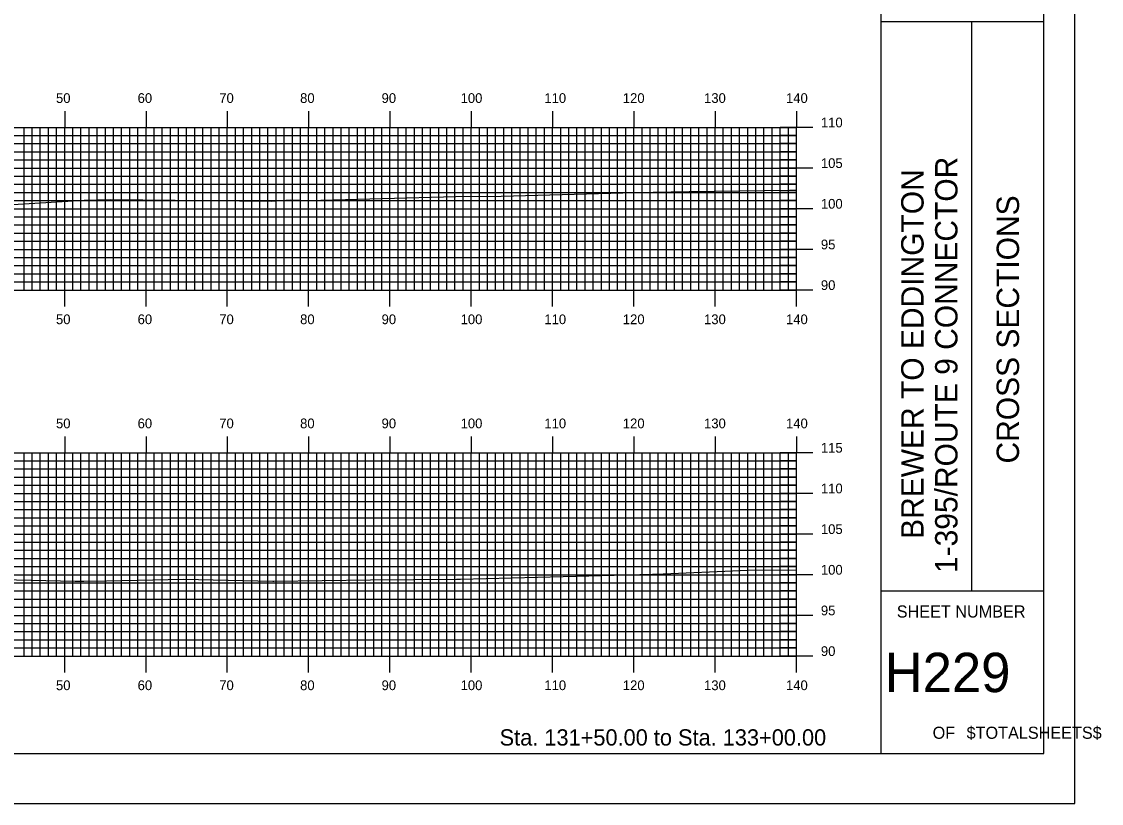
# Model space of a CAD drawing. Extents: x 1774383 to 1774727, y 442591 to 442811.
# Drawn here: x 1774593.9 to 1774726.7, y 442590.5 to 442686.7 of the extents above; entities that cross this region are included whole.
import ezdxf

# ---------------------------------------------------------------- set-up
doc = ezdxf.new("R2010")
doc.units = 0
for name, color, linetype in [('BORDER', 7, 'Continuous'), ('H_V ANNOTATION', 7, 'Continuous'), ('MAJOR', 7, 'Continuous'), ('MINOR', 7, 'Continuous'), ('PLOT BOUNDARY', 7, 'Continuous'), ('S_Roadway_Centerline', 7, 'Continuous')]:
    doc.layers.add(name, color=color, linetype=linetype)

msp = doc.modelspace()

# ---------------------------------------------------------------- linework, layer by layer
at = {"layer": 'BORDER'}
for p, q in [((1774699.57, 442596.67), (1774699.57, 442806.67)), ((1774699.57, 442686.67), (1774719.57, 442686.67)), ((1774710.75, 442616.67), (1774710.75, 442686.67)), ((1774699.57, 442616.67), (1774719.57, 442616.67))]:
    msp.add_line(p, q, dxfattribs=at)
msp.add_lwpolyline([(1774399.57, 442596.67), (1774719.57, 442596.67), (1774719.57, 442806.67), (1774399.57, 442806.67)], close=True, dxfattribs=at)
at = {"layer": 'MAJOR'}
for p, q in [((1774599.17, 442675.67), (1774599.17, 442673.67)), ((1774609.17, 442675.67), (1774609.17, 442673.67)), ((1774619.17, 442675.67), (1774619.17, 442673.67)), ((1774629.17, 442675.67), (1774629.17, 442673.67)), ((1774639.17, 442675.67), (1774639.17, 442673.67)), ((1774649.17, 442675.67), (1774649.17, 442673.67)), ((1774659.17, 442675.67), (1774659.17, 442673.67)), ((1774669.17, 442675.67), (1774669.17, 442673.67)), ((1774679.17, 442675.67), (1774679.17, 442673.67)), ((1774689.17, 442675.67), (1774689.17, 442673.67)), ((1774409.17, 442673.67), (1774689.17, 442673.67)), ((1774409.17, 442673.67), (1774689.17, 442673.67)), ((1774599.17, 442653.67), (1774599.17, 442673.67)), ((1774609.17, 442653.67), (1774609.17, 442673.67)), ((1774619.17, 442653.67), (1774619.17, 442673.67)), ((1774629.17, 442653.67), (1774629.17, 442673.67)), ((1774639.17, 442653.67), (1774639.17, 442673.67)), ((1774649.17, 442653.67), (1774649.17, 442673.67)), ((1774659.17, 442653.67), (1774659.17, 442673.67)), ((1774669.17, 442653.67), (1774669.17, 442673.67)), ((1774679.17, 442653.67), (1774679.17, 442673.67)), ((1774691.18, 442673.67), (1774687.17, 442673.67)), ((1774689.17, 442653.67), (1774689.17, 442673.67)), ((1774689.17, 442653.67), (1774689.17, 442673.67)), ((1774409.17, 442668.67), (1774689.17, 442668.67)), ((1774691.18, 442668.67), (1774687.17, 442668.67)), ((1774409.17, 442663.67), (1774689.17, 442663.67)), ((1774691.18, 442663.67), (1774687.17, 442663.67)), ((1774409.17, 442658.67), (1774689.17, 442658.67)), ((1774691.18, 442658.67), (1774687.17, 442658.67)), ((1774409.17, 442653.67), (1774689.17, 442653.67)), ((1774409.17, 442653.67), (1774689.17, 442653.67)), ((1774599.17, 442651.66), (1774599.17, 442653.67)), ((1774609.17, 442651.66), (1774609.17, 442653.67)), ((1774619.17, 442651.66), (1774619.17, 442653.67)), ((1774629.17, 442651.66), (1774629.17, 442653.67)), ((1774639.17, 442651.66), (1774639.17, 442653.67)), ((1774649.17, 442651.66), (1774649.17, 442653.67)), ((1774659.17, 442651.66), (1774659.17, 442653.67)), ((1774669.17, 442651.66), (1774669.17, 442653.67)), ((1774679.17, 442651.66), (1774679.17, 442653.67)), ((1774691.18, 442653.67), (1774687.17, 442653.67)), ((1774689.17, 442651.66), (1774689.17, 442653.67)), ((1774599.17, 442635.67), (1774599.17, 442633.67)), ((1774609.17, 442635.67), (1774609.17, 442633.67)), ((1774619.17, 442635.67), (1774619.17, 442633.67)), ((1774629.17, 442635.67), (1774629.17, 442633.67)), ((1774639.17, 442635.67), (1774639.17, 442633.67)), ((1774649.17, 442635.67), (1774649.17, 442633.67)), ((1774659.17, 442635.67), (1774659.17, 442633.67)), ((1774669.17, 442635.67), (1774669.17, 442633.67)), ((1774679.17, 442635.67), (1774679.17, 442633.67)), ((1774689.17, 442635.67), (1774689.17, 442633.67)), ((1774409.17, 442633.67), (1774689.17, 442633.67)), ((1774409.17, 442633.67), (1774689.17, 442633.67)), ((1774599.17, 442608.67), (1774599.17, 442633.67)), ((1774609.17, 442608.67), (1774609.17, 442633.67)), ((1774619.17, 442608.67), (1774619.17, 442633.67)), ((1774629.17, 442608.67), (1774629.17, 442633.67)), ((1774639.17, 442608.67), (1774639.17, 442633.67)), ((1774649.17, 442608.67), (1774649.17, 442633.67)), ((1774659.17, 442608.67), (1774659.17, 442633.67)), ((1774669.17, 442608.67), (1774669.17, 442633.67)), ((1774679.17, 442608.67), (1774679.17, 442633.67)), ((1774691.18, 442633.67), (1774687.17, 442633.67)), ((1774689.17, 442608.67), (1774689.17, 442633.67)), ((1774689.17, 442608.67), (1774689.17, 442633.67)), ((1774409.17, 442628.67), (1774689.17, 442628.67)), ((1774691.18, 442628.67), (1774687.17, 442628.67)), ((1774409.17, 442623.67), (1774689.17, 442623.67)), ((1774691.18, 442623.67), (1774687.17, 442623.67)), ((1774409.17, 442618.67), (1774689.17, 442618.67)), ((1774691.18, 442618.67), (1774687.17, 442618.67)), ((1774409.17, 442613.67), (1774689.17, 442613.67)), ((1774691.18, 442613.67), (1774687.17, 442613.67)), ((1774409.17, 442608.67), (1774689.17, 442608.67)), ((1774409.17, 442608.67), (1774689.17, 442608.67)), ((1774599.17, 442606.66), (1774599.17, 442608.67)), ((1774609.17, 442606.66), (1774609.17, 442608.67)), ((1774619.17, 442606.66), (1774619.17, 442608.67)), ((1774629.17, 442606.66), (1774629.17, 442608.67)), ((1774639.17, 442606.66), (1774639.17, 442608.67)), ((1774649.17, 442606.66), (1774649.17, 442608.67)), ((1774659.17, 442606.66), (1774659.17, 442608.67)), ((1774669.17, 442606.66), (1774669.17, 442608.67)), ((1774679.17, 442606.66), (1774679.17, 442608.67)), ((1774691.18, 442608.67), (1774687.17, 442608.67)), ((1774689.17, 442606.66), (1774689.17, 442608.67))]:
    msp.add_line(p, q, dxfattribs=at)
at = {"layer": 'MINOR'}
for p, q in [((1774594.17, 442653.67), (1774594.17, 442673.67)), ((1774595.17, 442653.67), (1774595.17, 442673.67)), ((1774596.17, 442653.67), (1774596.17, 442673.67)), ((1774597.17, 442653.67), (1774597.17, 442673.67)), ((1774598.17, 442653.67), (1774598.17, 442673.67)), ((1774600.17, 442653.67), (1774600.17, 442673.67)), ((1774601.17, 442653.67), (1774601.17, 442673.67)), ((1774602.17, 442653.67), (1774602.17, 442673.67)), ((1774603.17, 442653.67), (1774603.17, 442673.67)), ((1774604.17, 442653.67), (1774604.17, 442673.67)), ((1774605.17, 442653.67), (1774605.17, 442673.67)), ((1774606.17, 442653.67), (1774606.17, 442673.67)), ((1774607.17, 442653.67), (1774607.17, 442673.67)), ((1774608.17, 442653.67), (1774608.17, 442673.67)), ((1774610.17, 442653.67), (1774610.17, 442673.67)), ((1774611.17, 442653.67), (1774611.17, 442673.67)), ((1774612.17, 442653.67), (1774612.17, 442673.67)), ((1774613.17, 442653.67), (1774613.17, 442673.67)), ((1774614.17, 442653.67), (1774614.17, 442673.67)), ((1774615.17, 442653.67), (1774615.17, 442673.67)), ((1774616.17, 442653.67), (1774616.17, 442673.67)), ((1774617.17, 442653.67), (1774617.17, 442673.67)), ((1774618.17, 442653.67), (1774618.17, 442673.67)), ((1774620.17, 442653.67), (1774620.17, 442673.67)), ((1774621.17, 442653.67), (1774621.17, 442673.67)), ((1774622.17, 442653.67), (1774622.17, 442673.67)), ((1774623.17, 442653.67), (1774623.17, 442673.67)), ((1774624.17, 442653.67), (1774624.17, 442673.67)), ((1774625.17, 442653.67), (1774625.17, 442673.67)), ((1774626.17, 442653.67), (1774626.17, 442673.67)), ((1774627.17, 442653.67), (1774627.17, 442673.67)), ((1774628.17, 442653.67), (1774628.17, 442673.67)), ((1774630.17, 442653.67), (1774630.17, 442673.67)), ((1774631.17, 442653.67), (1774631.17, 442673.67)), ((1774632.17, 442653.67), (1774632.17, 442673.67)), ((1774633.17, 442653.67), (1774633.17, 442673.67)), ((1774634.17, 442653.67), (1774634.17, 442673.67)), ((1774635.17, 442653.67), (1774635.17, 442673.67)), ((1774636.17, 442653.67), (1774636.17, 442673.67)), ((1774637.17, 442653.67), (1774637.17, 442673.67)), ((1774638.17, 442653.67), (1774638.17, 442673.67)), ((1774640.17, 442653.67), (1774640.17, 442673.67)), ((1774641.17, 442653.67), (1774641.17, 442673.67)), ((1774642.17, 442653.67), (1774642.17, 442673.67)), ((1774643.17, 442653.67), (1774643.17, 442673.67)), ((1774644.17, 442653.67), (1774644.17, 442673.67)), ((1774645.17, 442653.67), (1774645.17, 442673.67)), ((1774646.17, 442653.67), (1774646.17, 442673.67)), ((1774647.17, 442653.67), (1774647.17, 442673.67)), ((1774648.17, 442653.67), (1774648.17, 442673.67)), ((1774650.17, 442653.67), (1774650.17, 442673.67)), ((1774651.17, 442653.67), (1774651.17, 442673.67)), ((1774652.17, 442653.67), (1774652.17, 442673.67)), ((1774653.17, 442653.67), (1774653.17, 442673.67)), ((1774654.17, 442653.67), (1774654.17, 442673.67)), ((1774655.17, 442653.67), (1774655.17, 442673.67)), ((1774656.17, 442653.67), (1774656.17, 442673.67)), ((1774657.17, 442653.67), (1774657.17, 442673.67)), ((1774658.17, 442653.67), (1774658.17, 442673.67)), ((1774660.17, 442653.67), (1774660.17, 442673.67)), ((1774661.17, 442653.67), (1774661.17, 442673.67)), ((1774662.17, 442653.67), (1774662.17, 442673.67)), ((1774663.17, 442653.67), (1774663.17, 442673.67)), ((1774664.17, 442653.67), (1774664.17, 442673.67)), ((1774665.17, 442653.67), (1774665.17, 442673.67)), ((1774666.17, 442653.67), (1774666.17, 442673.67)), ((1774667.17, 442653.67), (1774667.17, 442673.67)), ((1774668.17, 442653.67), (1774668.17, 442673.67)), ((1774670.17, 442653.67), (1774670.17, 442673.67)), ((1774671.17, 442653.67), (1774671.17, 442673.67)), ((1774672.17, 442653.67), (1774672.17, 442673.67)), ((1774673.17, 442653.67), (1774673.17, 442673.67)), ((1774674.17, 442653.67), (1774674.17, 442673.67)), ((1774675.17, 442653.67), (1774675.17, 442673.67)), ((1774676.17, 442653.67), (1774676.17, 442673.67)), ((1774677.17, 442653.67), (1774677.17, 442673.67)), ((1774678.17, 442653.67), (1774678.17, 442673.67)), ((1774680.17, 442653.67), (1774680.17, 442673.67)), ((1774681.17, 442653.67), (1774681.17, 442673.67)), ((1774682.17, 442653.67), (1774682.17, 442673.67)), ((1774683.17, 442653.67), (1774683.17, 442673.67)), ((1774684.17, 442653.67), (1774684.17, 442673.67)), ((1774685.17, 442653.67), (1774685.17, 442673.67)), ((1774686.17, 442653.67), (1774686.17, 442673.67)), ((1774687.17, 442653.67), (1774687.17, 442673.67)), ((1774688.17, 442653.67), (1774688.17, 442673.67)), ((1774409.17, 442672.67), (1774689.17, 442672.67)), ((1774409.17, 442671.67), (1774689.17, 442671.67)), ((1774689.17, 442672.67), (1774687.17, 442672.67)), ((1774689.17, 442671.67), (1774687.17, 442671.67)), ((1774409.17, 442670.67), (1774689.17, 442670.67)), ((1774689.17, 442670.67), (1774687.17, 442670.67)), ((1774409.17, 442669.67), (1774689.17, 442669.67)), ((1774689.17, 442669.67), (1774687.17, 442669.67)), ((1774409.17, 442667.67), (1774689.17, 442667.67)), ((1774689.17, 442667.67), (1774687.17, 442667.67)), ((1774409.17, 442666.67), (1774689.17, 442666.67)), ((1774689.17, 442666.67), (1774687.17, 442666.67)), ((1774409.17, 442665.67), (1774689.17, 442665.67)), ((1774689.17, 442665.67), (1774687.17, 442665.67)), ((1774409.17, 442664.67), (1774689.17, 442664.67)), ((1774689.17, 442664.67), (1774687.17, 442664.67)), ((1774409.17, 442662.67), (1774689.17, 442662.67)), ((1774689.17, 442662.67), (1774687.17, 442662.67)), ((1774409.17, 442661.67), (1774689.17, 442661.67)), ((1774689.17, 442661.67), (1774687.17, 442661.67)), ((1774409.17, 442660.67), (1774689.17, 442660.67)), ((1774409.17, 442659.67), (1774689.17, 442659.67)), ((1774689.17, 442660.67), (1774687.17, 442660.67)), ((1774689.17, 442659.67), (1774687.17, 442659.67)), ((1774409.17, 442657.67), (1774689.17, 442657.67)), ((1774689.17, 442657.67), (1774687.17, 442657.67)), ((1774409.17, 442656.67), (1774689.17, 442656.67)), ((1774409.17, 442655.67), (1774689.17, 442655.67)), ((1774689.17, 442656.67), (1774687.17, 442656.67)), ((1774689.17, 442655.67), (1774687.17, 442655.67)), ((1774409.17, 442654.67), (1774689.17, 442654.67)), ((1774689.17, 442654.67), (1774687.17, 442654.67)), ((1774594.17, 442608.67), (1774594.17, 442633.67)), ((1774595.17, 442608.67), (1774595.17, 442633.67)), ((1774596.17, 442608.67), (1774596.17, 442633.67)), ((1774597.17, 442608.67), (1774597.17, 442633.67)), ((1774598.17, 442608.67), (1774598.17, 442633.67)), ((1774600.17, 442608.67), (1774600.17, 442633.67)), ((1774601.17, 442608.67), (1774601.17, 442633.67)), ((1774602.17, 442608.67), (1774602.17, 442633.67)), ((1774603.17, 442608.67), (1774603.17, 442633.67)), ((1774604.17, 442608.67), (1774604.17, 442633.67)), ((1774605.17, 442608.67), (1774605.17, 442633.67)), ((1774606.17, 442608.67), (1774606.17, 442633.67)), ((1774607.17, 442608.67), (1774607.17, 442633.67)), ((1774608.17, 442608.67), (1774608.17, 442633.67)), ((1774610.17, 442608.67), (1774610.17, 442633.67)), ((1774611.17, 442608.67), (1774611.17, 442633.67)), ((1774612.17, 442608.67), (1774612.17, 442633.67)), ((1774613.17, 442608.67), (1774613.17, 442633.67)), ((1774614.17, 442608.67), (1774614.17, 442633.67)), ((1774615.17, 442608.67), (1774615.17, 442633.67)), ((1774616.17, 442608.67), (1774616.17, 442633.67)), ((1774617.17, 442608.67), (1774617.17, 442633.67)), ((1774618.17, 442608.67), (1774618.17, 442633.67)), ((1774620.17, 442608.67), (1774620.17, 442633.67)), ((1774621.17, 442608.67), (1774621.17, 442633.67)), ((1774622.17, 442608.67), (1774622.17, 442633.67)), ((1774623.17, 442608.67), (1774623.17, 442633.67)), ((1774624.17, 442608.67), (1774624.17, 442633.67)), ((1774625.17, 442608.67), (1774625.17, 442633.67)), ((1774626.17, 442608.67), (1774626.17, 442633.67)), ((1774627.17, 442608.67), (1774627.17, 442633.67)), ((1774628.17, 442608.67), (1774628.17, 442633.67)), ((1774630.17, 442608.67), (1774630.17, 442633.67)), ((1774631.17, 442608.67), (1774631.17, 442633.67)), ((1774632.17, 442608.67), (1774632.17, 442633.67)), ((1774633.17, 442608.67), (1774633.17, 442633.67)), ((1774634.17, 442608.67), (1774634.17, 442633.67)), ((1774635.17, 442608.67), (1774635.17, 442633.67)), ((1774636.17, 442608.67), (1774636.17, 442633.67)), ((1774637.17, 442608.67), (1774637.17, 442633.67)), ((1774638.17, 442608.67), (1774638.17, 442633.67)), ((1774640.17, 442608.67), (1774640.17, 442633.67)), ((1774641.17, 442608.67), (1774641.17, 442633.67)), ((1774642.17, 442608.67), (1774642.17, 442633.67)), ((1774643.17, 442608.67), (1774643.17, 442633.67)), ((1774644.17, 442608.67), (1774644.17, 442633.67)), ((1774645.17, 442608.67), (1774645.17, 442633.67)), ((1774646.17, 442608.67), (1774646.17, 442633.67)), ((1774647.17, 442608.67), (1774647.17, 442633.67)), ((1774648.17, 442608.67), (1774648.17, 442633.67)), ((1774650.17, 442608.67), (1774650.17, 442633.67)), ((1774651.17, 442608.67), (1774651.17, 442633.67)), ((1774652.17, 442608.67), (1774652.17, 442633.67)), ((1774653.17, 442608.67), (1774653.17, 442633.67)), ((1774654.17, 442608.67), (1774654.17, 442633.67)), ((1774655.17, 442608.67), (1774655.17, 442633.67)), ((1774656.17, 442608.67), (1774656.17, 442633.67)), ((1774657.17, 442608.67), (1774657.17, 442633.67)), ((1774658.17, 442608.67), (1774658.17, 442633.67)), ((1774660.17, 442608.67), (1774660.17, 442633.67)), ((1774661.17, 442608.67), (1774661.17, 442633.67)), ((1774662.17, 442608.67), (1774662.17, 442633.67)), ((1774663.17, 442608.67), (1774663.17, 442633.67)), ((1774664.17, 442608.67), (1774664.17, 442633.67)), ((1774665.17, 442608.67), (1774665.17, 442633.67)), ((1774666.17, 442608.67), (1774666.17, 442633.67)), ((1774667.17, 442608.67), (1774667.17, 442633.67)), ((1774668.17, 442608.67), (1774668.17, 442633.67)), ((1774670.17, 442608.67), (1774670.17, 442633.67)), ((1774671.17, 442608.67), (1774671.17, 442633.67)), ((1774672.17, 442608.67), (1774672.17, 442633.67)), ((1774673.17, 442608.67), (1774673.17, 442633.67)), ((1774674.17, 442608.67), (1774674.17, 442633.67)), ((1774675.17, 442608.67), (1774675.17, 442633.67)), ((1774676.17, 442608.67), (1774676.17, 442633.67)), ((1774677.17, 442608.67), (1774677.17, 442633.67)), ((1774678.17, 442608.67), (1774678.17, 442633.67)), ((1774680.17, 442608.67), (1774680.17, 442633.67)), ((1774681.17, 442608.67), (1774681.17, 442633.67)), ((1774682.17, 442608.67), (1774682.17, 442633.67)), ((1774683.17, 442608.67), (1774683.17, 442633.67)), ((1774684.17, 442608.67), (1774684.17, 442633.67)), ((1774685.17, 442608.67), (1774685.17, 442633.67)), ((1774686.17, 442608.67), (1774686.17, 442633.67)), ((1774687.17, 442608.67), (1774687.17, 442633.67)), ((1774688.17, 442608.67), (1774688.17, 442633.67)), ((1774409.17, 442632.67), (1774689.17, 442632.67)), ((1774689.17, 442632.67), (1774687.17, 442632.67)), ((1774409.17, 442631.67), (1774689.17, 442631.67)), ((1774409.17, 442630.67), (1774689.17, 442630.67)), ((1774689.17, 442631.67), (1774687.17, 442631.67)), ((1774689.17, 442630.67), (1774687.17, 442630.67)), ((1774409.17, 442629.67), (1774689.17, 442629.67)), ((1774689.17, 442629.67), (1774687.17, 442629.67)), ((1774409.17, 442627.67), (1774689.17, 442627.67)), ((1774409.17, 442626.67), (1774689.17, 442626.67)), ((1774689.17, 442627.67), (1774687.17, 442627.67)), ((1774689.17, 442626.67), (1774687.17, 442626.67)), ((1774409.17, 442625.67), (1774689.17, 442625.67)), ((1774689.17, 442625.67), (1774687.17, 442625.67)), ((1774409.17, 442624.67), (1774689.17, 442624.67)), ((1774689.17, 442624.67), (1774687.17, 442624.67)), ((1774409.17, 442622.67), (1774689.17, 442622.67)), ((1774689.17, 442622.67), (1774687.17, 442622.67)), ((1774409.17, 442621.67), (1774689.17, 442621.67)), ((1774689.17, 442621.67), (1774687.17, 442621.67)), ((1774409.17, 442620.67), (1774689.17, 442620.67)), ((1774689.17, 442620.67), (1774687.17, 442620.67)), ((1774409.17, 442619.67), (1774689.17, 442619.67)), ((1774689.17, 442619.67), (1774687.17, 442619.67)), ((1774409.17, 442617.67), (1774689.17, 442617.67)), ((1774689.17, 442617.67), (1774687.17, 442617.67)), ((1774409.17, 442616.67), (1774689.17, 442616.67)), ((1774689.17, 442616.67), (1774687.17, 442616.67)), ((1774409.17, 442615.67), (1774689.17, 442615.67)), ((1774409.17, 442614.67), (1774689.17, 442614.67)), ((1774689.17, 442615.67), (1774687.17, 442615.67)), ((1774689.17, 442614.67), (1774687.17, 442614.67)), ((1774409.17, 442612.67), (1774689.17, 442612.67)), ((1774689.17, 442612.67), (1774687.17, 442612.67)), ((1774409.17, 442611.67), (1774689.17, 442611.67)), ((1774409.17, 442610.67), (1774689.17, 442610.67)), ((1774689.17, 442611.67), (1774687.17, 442611.67)), ((1774689.17, 442610.67), (1774687.17, 442610.67)), ((1774409.17, 442609.67), (1774689.17, 442609.67)), ((1774689.17, 442609.67), (1774687.17, 442609.67))]:
    msp.add_line(p, q, dxfattribs=at)
at = {"layer": 'PLOT BOUNDARY'}
msp.add_lwpolyline([(1774383.39, 442590.55), (1774723.39, 442590.55), (1774723.39, 442810.55), (1774383.39, 442810.55)], close=True, dxfattribs=at)
at = {"layer": 'S_Roadway_Centerline'}
for points in [[(1774581.93, 442663.54), (1774601.55, 442664.72), (1774603.22, 442664.77), (1774604.86, 442664.79), (1774624.59, 442664.6), (1774626.96, 442664.74), (1774629.16, 442664.69), (1774647.26, 442665.15), (1774652.84, 442665.23), (1774669.33, 442665.67), (1774675.95, 442665.78), (1774688.29, 442665.95), (1774689.17, 442665.96)], [(1774578.72, 442618.36), (1774600.44, 442617.87), (1774601.53, 442617.87), (1774604.32, 442617.91), (1774613.77, 442618.13), (1774624.76, 442617.87), (1774624.87, 442617.87), (1774636.77, 442618.03), (1774647.35, 442618.1), (1774647.57, 442618.1), (1774647.85, 442618.1), (1774660.46, 442618.46), (1774671.47, 442618.74), (1774671.82, 442618.75), (1774683.18, 442619.24), (1774689.17, 442619.25)]]:
    msp.add_lwpolyline(points, dxfattribs=at)

# ---------------------------------------------------------------- texts
at = {"layer": 'BORDER'}
for s, p in [('1-395/ROUTE 9 CONNECTOR', (1774708.97, 442618.87)), ('BREWER TO EDDINGTON', (1774704.8, 442623.07)), ('CROSS SECTIONS', (1774716.54, 442632.34))]:
    msp.add_text(s, height=2.7557, rotation=90, dxfattribs=at).set_placement(p)
for s, height, p in [('SHEET NUMBER', 1.4905, (1774701.5, 442613.4)), ('H229', 4.839, (1774700.01, 442604.23)), ('OF', 1.491, (1774705.91, 442598.49)), ('$TOTALSHEETS$', 1.4905, (1774710.09, 442598.49))]:
    msp.add_text(s, height=height, dxfattribs=at).set_placement(p)
at = {"layer": 'H_V ANNOTATION'}
for s, height, p in [('50', 1.2, (1774598.1, 442676.67)), ('60', 1.2, (1774608.14, 442676.67)), ('70', 1.2, (1774618.18, 442676.67)), ('80', 1.2, (1774628.12, 442676.67)), ('90', 1.2, (1774638.14, 442676.67)), ('100', 1.2, (1774647.86, 442676.67)), ('110', 1.2, (1774658.16, 442676.67)), ('120', 1.2, (1774667.81, 442676.67)), ('130', 1.2, (1774677.8, 442676.67)), ('140', 1.2, (1774687.88, 442676.67)), ('110', 1.2, (1774692.17, 442673.67)), ('105', 1.2, (1774692.17, 442668.67)), ('100', 1.2, (1774692.17, 442663.67)), ('95', 1.2, (1774692.17, 442658.67)), ('90', 1.2, (1774692.17, 442653.67)), ('50', 1.2, (1774598.1, 442649.47)), ('60', 1.2, (1774608.14, 442649.47)), ('70', 1.2, (1774618.18, 442649.47)), ('80', 1.2, (1774628.12, 442649.47)), ('90', 1.2, (1774638.14, 442649.47)), ('100', 1.2, (1774647.86, 442649.47)), ('110', 1.2, (1774658.16, 442649.47)), ('120', 1.2, (1774667.81, 442649.47)), ('130', 1.2, (1774677.8, 442649.47)), ('140', 1.2, (1774687.88, 442649.47)), ('50', 1.2, (1774598.1, 442636.67)), ('60', 1.2, (1774608.14, 442636.67)), ('70', 1.2, (1774618.18, 442636.67)), ('80', 1.2, (1774628.12, 442636.67)), ('90', 1.2, (1774638.14, 442636.67)), ('100', 1.2, (1774647.86, 442636.67)), ('110', 1.2, (1774658.16, 442636.67)), ('120', 1.2, (1774667.81, 442636.67)), ('130', 1.2, (1774677.8, 442636.67)), ('140', 1.2, (1774687.88, 442636.67)), ('115', 1.2, (1774692.17, 442633.67)), ('110', 1.2, (1774692.17, 442628.67)), ('105', 1.2, (1774692.17, 442623.67)), ('100', 1.2, (1774692.17, 442618.67)), ('95', 1.2, (1774692.17, 442613.67)), ('90', 1.2, (1774692.17, 442608.67)), ('50', 1.2, (1774598.1, 442604.47)), ('60', 1.2, (1774608.14, 442604.47)), ('70', 1.2, (1774618.18, 442604.47)), ('80', 1.2, (1774628.12, 442604.47)), ('90', 1.2, (1774638.14, 442604.47)), ('100', 1.2, (1774647.86, 442604.47)), ('110', 1.2, (1774658.16, 442604.47)), ('120', 1.2, (1774667.81, 442604.47)), ('130', 1.2, (1774677.8, 442604.47)), ('140', 1.2, (1774687.88, 442604.47)), ('Sta. 131+50.00 to Sta. 133+00.00', 2.0004, (1774652.66, 442597.66))]:
    msp.add_text(s, height=height, dxfattribs=at).set_placement(p)

doc.saveas('drawing.dxf')
